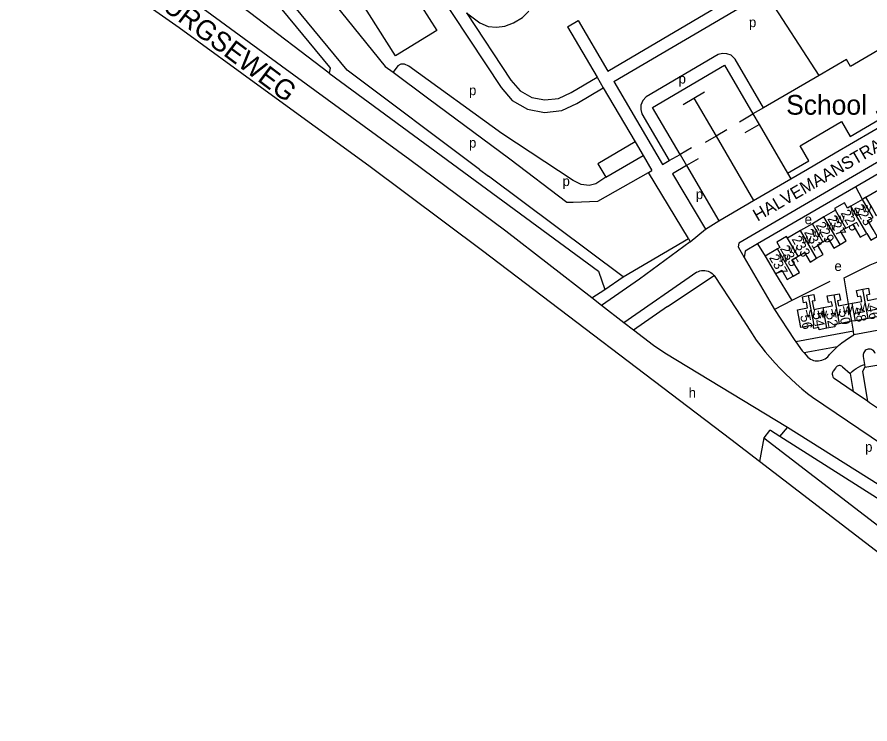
# Model space of a CAD drawing. Extents: x 158356 to 159894, y 383831 to 385260.
# Drawn here: x 158355.9 to 158701.2, y 383902.1 to 384188.4 of the extents above; entities that cross this region are included whole.
import ezdxf

# ---------------------------------------------------------------- set-up
doc = ezdxf.new("R2010")
doc.units = 0
for name, color, linetype in [('BLT_Basislijn', 7, 'Continuous'), ('BLT_Bebouwing', 7, 'Continuous'), ('BLT_Bebouwing_beschrifting', 7, 'Continuous'), ('BLT_Centroide', 7, 'Continuous'), ('BLT_Huisnummer', 7, 'Continuous'), ('BLT_Huisnummer_ tussenligend', 7, 'Continuous'), ('BLT_Onderdoorgang_en_onderverdeling', 7, 'Continuous'), ('BLT_Onderverdeling_panden', 7, 'Continuous'), ('BLT_Straatnaam', 7, 'Continuous'), ('BLT_Straatnaam_hoofdweg', 7, 'Continuous'), ('BLT_Vlakafsluiter', 7, 'Continuous')]:
    doc.layers.add(name, color=color, linetype=linetype)

msp = doc.modelspace()

# ---------------------------------------------------------------- linework, layer by layer
at = {"layer": 'BLT_Basislijn'}
for p, q in [((158578.7, 384184.41), (158583.01, 384186.94)), ((158578.7, 384184.41), (158590.72, 384163.98)), ((158583.01, 384186.94), (158595.03, 384166.51)), ((158639.73, 384173.14), (158610.57, 384156.06)), ((158508.16, 384166), (158522.06, 384155.66)), ((158593.25, 384159.67), (158606.12, 384137.79)), ((158597.56, 384162.2), (158617.27, 384128.7)), ((158629.9, 384155.55), (158634.25, 384158.12)), ((158522.06, 384155.66), (158555.35, 384130.9)), ((158625.56, 384152.99), (158629.9, 384155.55)), ((158629.9, 384155.55), (158638.9, 384140.17)), ((158648.4, 384145.96), (158653.81, 384149.12)), ((158643.26, 384142.74), (158638.9, 384140.17)), ((158650.71, 384141.6), (158656.29, 384144.87)), ((158638.9, 384140.17), (158634.53, 384137.6)), ((158638.9, 384140.17), (158654.09, 384114.05)), ((158606.12, 384137.79), (158609.34, 384132.32)), ((158629.01, 384135.4), (158624.32, 384132.73)), ((158594.23, 384123.49), (158609.34, 384132.32)), ((158609.34, 384132.32), (158612.93, 384126.22)), ((158619.98, 384130.25), (158624.32, 384132.73)), ((158624.32, 384132.73), (158626.93, 384128.25)), ((158617.27, 384128.7), (158619.98, 384130.25)), ((158631.6, 384131.01), (158626.93, 384128.25)), ((158543.13, 384126.68), (158546.72, 384123.99)), ((158611.5, 384125.4), (158612.93, 384126.22)), ((158627.68, 384098.63), (158611.5, 384125.4)), ((158626.93, 384128.25), (158621.25, 384124.9)), ((158621.25, 384124.9), (158634.57, 384102.4)), ((158626.93, 384128.25), (158640, 384105.85)), ((158667.8, 384125.16), (158669.15, 384122.83)), ((158601.25, 384083.15), (158546.72, 384123.99)), ((158654.09, 384114.05), (158669.15, 384122.83)), ((158695.47, 384119.63), (158655.72, 384096.51)), ((158698.19, 384114.54), (158695.47, 384119.63)), ((158699.54, 384115.39), (158698.19, 384114.54)), ((158640, 384105.85), (158654.09, 384114.05)), ((158634.57, 384102.4), (158640, 384105.85)), ((158588.63, 384074.62), (158553.77, 384101.62)), ((158628.45, 384097.36), (158634.57, 384102.4)), ((158601.25, 384083.15), (158627.68, 384098.63)), ((158655.72, 384096.51), (158658.75, 384091.51)), ((158631.15, 384085.02), (158601.61, 384064.57)), ((158619.3, 384071.18), (158638.1, 384083.74)), ((158662.9, 384084.37), (158669.59, 384073.64)), ((158593.84, 384078.08), (158601.25, 384083.15)), ((158684.93, 384081.32), (158669.59, 384073.64)), ((158588.63, 384074.62), (158593.84, 384078.08)), ((158592.55, 384071.59), (158588.63, 384074.62)), ((158669.59, 384073.64), (158662.55, 384069.96)), ((158601.61, 384064.57), (158592.55, 384071.59)), ((158619.3, 384071.18), (158605.45, 384061.6)), ((158662.55, 384069.96), (158670.49, 384057.77)), ((158605.45, 384061.6), (158601.61, 384064.57)), ((158694.48, 384061.13), (158693.9, 384065.16)), ((158727.11, 384065.73), (158694.69, 384059.64)), ((158694.48, 384061.13), (158671.22, 384056.78)), ((158694.69, 384059.64), (158694.48, 384061.13)), ((158687.89, 384054.81), (158674.59, 384052.32)), ((158674.59, 384052.32), (158676.02, 384050.63)), ((158698.46, 384050.9), (158698.96, 384047.67)), ((158687.31, 384046.22), (158686.35, 384044.98)), ((158690.15, 384046.77), (158693.23, 384044.02)), ((158699.14, 384046.54), (158698.16, 384044.84)), ((158698.96, 384047.67), (158699.14, 384046.54)), ((158699.14, 384046.54), (158704.05, 384047.44)), ((158693.23, 384044.02), (158694.45, 384036.7)), ((158698.16, 384044.84), (158700.18, 384032.75)), ((158694.45, 384036.7), (158686.76, 384041.95)), ((158699.39, 384033.33), (158694.45, 384036.7)), ((158677.95, 384034.41), (158706.27, 384015.3)), ((158700.18, 384032.75), (158699.39, 384033.33)), ((158719.42, 383989.69), (158667.79, 384022.18)), ((158656.47, 384008.34), (158644.82, 384017.27)), ((158733.69, 383949.17), (158656.47, 384008.34))]:
    msp.add_line(p, q, dxfattribs=at)
for points in [[(158411.05, 384254.61), (158482.47, 384168.03), (158482.74, 384167.63), (158482.31, 384165.65)], [(158482.31, 384165.65), (158417.72, 384214.84), (158386.28, 384237.31), (158383.92, 384237.99), (158377.96, 384236.95)], [(158499.82, 384238.62), (158551.85, 384159.77), (158556.33, 384154.59), (158562.5, 384151.05), (158569.43, 384149.73), (158576.44, 384150.51), (158582.59, 384153.39), (158593.25, 384159.67)], [(158498.33, 384128.13), (158454.84, 384159.75), (158421.6, 384183.98), (158374.82, 384216.83), (158355.92, 384229.65)], [(158553.77, 384101.62), (158514.89, 384130.54), (158462.93, 384168.42), (158432.71, 384190.6), (158412.8, 384204.65), (158387.75, 384219.8), (158378.82, 384225.15)], [(158680.64, 384164.75), (158659.4, 384197.49), (158701.12, 384225.27)], [(158595.03, 384166.51), (158651.21, 384199.6), (158654.32, 384201.89), (158656.74, 384204.69), (158658.46, 384207.97), (158659.42, 384211.54), (158659.55, 384215.25), (158658.88, 384218.88), (158657.33, 384222.31)], [(158597.56, 384162.2), (158653.97, 384195.42), (158657.73, 384198.2), (158660.9, 384201.85), (158663.14, 384206.13), (158664.4, 384210.8), (158664.57, 384215.62), (158663.68, 384220.38), (158662.9, 384222.13)], [(158466.15, 384216.37), (158504.98, 384168.37), (158508.16, 384166)], [(158543.13, 384126.68), (158489.58, 384166.83), (158454.86, 384208.9)], [(158537.85, 384190.07), (158543.32, 384186.02), (158546.64, 384184.5), (158550, 384184.31), (158553.33, 384184.72), (158556.89, 384186.05), (158560.48, 384188.16), (158563.05, 384190.76)], [(158537.85, 384190.07), (158555.85, 384162.79), (158559.56, 384158.5), (158564.26, 384155.81), (158569.63, 384154.79), (158575.07, 384155.39), (158580.26, 384157.82), (158590.72, 384163.98)], [(158785.32, 384174.66), (158783.94, 384176.68), (158782.64, 384177.18), (158781.63, 384177.11), (158748.8, 384155.41), (158738.53, 384149.56), (158648.13, 384096.77), (158647.84, 384095.35), (158650.22, 384090.93)], [(158658.13, 384151.64), (158646.57, 384171.36), (158645.01, 384172.86), (158643.29, 384173.53), (158641.55, 384173.66), (158639.73, 384173.14)], [(158594.23, 384123.49), (158590.29, 384120.86), (158587.52, 384120.11), (158584.23, 384120.53), (158581.09, 384122.15), (158552.15, 384141.15), (158514.49, 384168.51), (158512.8, 384169.31), (158511.27, 384169.25), (158510.07, 384168.54), (158508.16, 384166)], [(158624.32, 384132.73), (158613.1, 384151.74), (158642.26, 384168.83), (158653.81, 384149.12)], [(158482.31, 384165.65), (158591.31, 384085.44), (158593.84, 384078.08)], [(158610.57, 384156.06), (158609.22, 384154.59), (158608.39, 384152.68), (158608.39, 384150.92), (158608.8, 384149.2), (158619.98, 384130.25)], [(158669.15, 384122.83), (158675.92, 384126.78), (158687.07, 384133.33), (158709.41, 384146.37)], [(158745.84, 384148.93), (158695.47, 384119.63)], [(158606.12, 384137.79), (158591.01, 384128.98), (158594.23, 384123.49)], [(158555.35, 384130.9), (158578.51, 384113.34), (158581.11, 384113.43)], [(158644.82, 384017.27), (158544.29, 384093.64), (158498.33, 384128.13)], [(158581.11, 384113.43), (158591.1, 384113.76), (158611.5, 384125.4)], [(158627.68, 384098.63), (158628.45, 384097.36), (158607.85, 384082.24), (158592.55, 384071.59)], [(158655.72, 384096.51), (158650.65, 384093.56), (158650.22, 384090.93)], [(158650.22, 384090.93), (158662.55, 384069.96)], [(158692.58, 384072.17), (158690.7, 384082.78), (158701.23, 384088.02), (158711.39, 384092.06)], [(158631.15, 384085.02), (158631.75, 384085.31), (158632.38, 384085.53), (158633.02, 384085.67), (158633.69, 384085.73), (158634.35, 384085.71), (158635.01, 384085.61), (158635.65, 384085.43), (158636.26, 384085.18), (158636.84, 384084.86), (158637.37, 384084.46), (158637.86, 384084.01), (158638.1, 384083.74)], [(158638.1, 384083.74), (158647.2, 384069.92), (158652.62, 384061.54), (158655.16, 384057.52)], [(158667.79, 384022.18), (158618.2, 384052.31), (158613.52, 384055.34), (158605.45, 384061.6)], [(158687.89, 384054.81), (158688.46, 384055.33), (158689.78, 384056.41), (158691.15, 384057.43), (158692.56, 384058.38), (158694.02, 384059.27), (158694.69, 384059.64)], [(158655.16, 384057.52), (158656.97, 384055.12), (158658.84, 384052.78), (158660.78, 384050.48), (158662.78, 384048.24), (158664.83, 384046.05), (158666.95, 384043.91), (158669.12, 384041.84), (158671.34, 384039.82), (158673.62, 384037.86), (158675.95, 384035.96), (158677.95, 384034.41)], [(158670.49, 384057.77), (158671.22, 384056.78)], [(158671.22, 384056.78), (158673.82, 384053.24), (158674.59, 384052.32)], [(158684.83, 384051.73), (158685.98, 384052.99), (158687.2, 384054.19), (158687.89, 384054.81)], [(158703.31, 384052.16), (158703.13, 384052.57), (158702.88, 384052.95), (158702.57, 384053.27), (158702.21, 384053.53), (158701.81, 384053.73), (158701.38, 384053.85), (158700.93, 384053.89), (158700.48, 384053.85), (158700.05, 384053.73), (158699.65, 384053.54), (158699.28, 384053.28), (158698.97, 384052.96), (158698.72, 384052.58), (158698.54, 384052.17), (158698.44, 384051.74), (158698.42, 384051.29), (158698.46, 384050.9)], [(158676.02, 384050.63), (158676.55, 384050.2), (158677.13, 384049.83), (158677.75, 384049.54), (158678.4, 384049.32), (158679.07, 384049.18), (158679.75, 384049.11), (158680.43, 384049.13), (158681.11, 384049.23), (158681.77, 384049.4), (158682.41, 384049.65), (158683.01, 384049.98), (158683.57, 384050.37), (158684.09, 384050.82), (158684.54, 384051.33), (158684.83, 384051.73)], [(158690.15, 384046.77), (158689.83, 384046.98), (158689.47, 384047.13), (158689.09, 384047.2), (158688.71, 384047.19), (158688.33, 384047.1), (158687.98, 384046.93), (158687.68, 384046.7), (158687.42, 384046.41), (158687.31, 384046.22)], [(158693.23, 384044.02), (158693.99, 384044.76), (158694.82, 384045.45), (158695.68, 384046.07), (158696.6, 384046.62), (158697.55, 384047.11), (158698.54, 384047.52), (158698.96, 384047.67)], [(158686.76, 384041.95), (158686.48, 384042.32), (158686.26, 384042.73), (158686.12, 384043.17), (158686.06, 384043.62), (158686.07, 384044.09), (158686.17, 384044.54), (158686.35, 384044.98)], [(158706.34, 384028.61), (158701.03, 384032.11), (158700.18, 384032.75)], [(158660.93, 384020.95), (158660.58, 384020.88), (158658.2, 384017.9)], [(158658.2, 384017.9), (158708.3, 383979.52), (158740.71, 383955.02), (158752.16, 383946.49), (158811.09, 383902.1)], [(158664.77, 384018.5), (158660.93, 384020.95)], [(158735.9, 383973.27), (158664.77, 384018.5)]]:
    msp.add_lwpolyline(points, dxfattribs=at)
msp.add_lwpolyline([(158484.6, 384211.57), (158501.08, 384221.87), (158525.85, 384182.86), (158509.08, 384172.69)], close=True, dxfattribs=at)
at = {"layer": 'BLT_Bebouwing'}
for p, q in [((158680.64, 384164.75), (158658.13, 384151.64)), ((158658.13, 384151.64), (158653.81, 384149.12)), ((158653.81, 384149.12), (158656.29, 384144.87)), ((158656.29, 384144.87), (158667.8, 384125.16)), ((158699.54, 384115.39), (158704.7, 384118.39)), ((158698.19, 384114.54), (158693.46, 384111.78)), ((158687.22, 384110.1), (158682.59, 384107.41)), ((158677.88, 384104.66), (158673.07, 384101.86)), ((158682.59, 384107.41), (158677.88, 384104.66)), ((158673.07, 384101.86), (158667.84, 384098.81)), ((158663.77, 384094.44), (158658.75, 384091.51)), ((158658.75, 384091.51), (158662.9, 384084.37)), ((158692.58, 384072.17), (158694, 384072.44)), ((158700.42, 384066.32), (158695.34, 384065.36)), ((158705.5, 384067.27), (158700.42, 384066.32)), ((158693.9, 384065.16), (158688.77, 384064.19)), ((158695.34, 384065.36), (158693.9, 384065.16))]:
    msp.add_line(p, q, dxfattribs=at)
for points in [[(158667.8, 384125.16), (158676.4, 384130.2), (158672.9, 384136.25), (158689.65, 384146.01), (158693.17, 384139.96), (158705.59, 384147.24), (158703.87, 384150.07), (158727.74, 384164), (158724.56, 384169.43), (158722.43, 384168.03), (158718.12, 384175.42), (158720.33, 384176.7), (158717.13, 384182.18), (158693.28, 384168.27), (158691.73, 384171.21), (158680.64, 384164.75)], [(158702.49, 384107.17), (158700.71, 384110.22), (158698.19, 384114.54)], [(158711.15, 384107.09), (158712.66, 384104.41), (158710.25, 384103.05), (158708.69, 384105.66), (158706.48, 384109.44), (158703.89, 384107.93), (158702.06, 384111.07), (158699.54, 384115.39)], [(158693.46, 384111.78), (158692.14, 384111.02), (158690.91, 384113.14), (158686.84, 384110.77), (158687.22, 384110.1)], [(158691.46, 384102.82), (158694.21, 384104.42), (158697.24, 384099.21), (158699.88, 384100.74)], [(158699.88, 384100.74), (158701.6, 384098.03), (158704.12, 384099.55), (158702.52, 384102.28), (158700.39, 384105.95), (158702.49, 384107.17)], [(158689.1, 384096.23), (158691.62, 384097.69), (158689.34, 384101.59), (158691.46, 384102.82)], [(158667.84, 384098.81), (158667.47, 384099.44), (158663.52, 384097.14), (158664.76, 384095.01), (158663.77, 384094.44)], [(158679.58, 384090.68), (158682.19, 384092.21), (158679.94, 384096.08), (158682.13, 384097.36)], [(158682.13, 384097.36), (158684.33, 384098.64), (158686.59, 384094.76), (158689.1, 384096.23)], [(158670.17, 384083.46), (158672.62, 384084.89), (158669.62, 384090.03), (158672.17, 384091.52)], [(158672.17, 384091.52), (158674.72, 384093.01), (158676.96, 384089.16), (158679.58, 384090.68)], [(158662.9, 384084.37), (158665.48, 384085.87), (158667.71, 384082.04), (158670.17, 384083.46)], [(158694, 384072.44), (158697.89, 384073.17), (158697.49, 384075.29), (158696.3, 384075.07), (158695.81, 384077.65), (158698.27, 384078.11)], [(158698.27, 384078.11), (158700.55, 384078.54), (158701.03, 384075.96), (158699.85, 384075.74), (158700.25, 384073.62), (158704.16, 384074.35)], [(158678.26, 384063.55), (158673.26, 384062.61), (158671.9, 384069.83), (158675.87, 384070.58), (158675.45, 384072.84), (158674.33, 384072.63), (158673.86, 384075.11), (158676.16, 384075.55)], [(158676.16, 384075.55), (158678.48, 384075.99), (158678.95, 384073.5), (158677.83, 384073.29), (158678.45, 384069.97), (158682.23, 384070.68)], [(158682.23, 384070.68), (158686, 384071.39), (158685.68, 384073.07), (158684.37, 384072.82), (158683.89, 384075.4), (158686.53, 384075.9)], [(158686.53, 384075.9), (158688.73, 384076.31), (158689.21, 384073.73), (158688, 384073.51), (158688.4, 384071.38), (158692.58, 384072.17)], [(158683.8, 384062.36), (158680.62, 384061.76), (158680.46, 384062.6), (158678.5, 384062.23), (158678.26, 384063.55)], [(158688.77, 384064.19), (158686.83, 384063.82), (158686.99, 384062.96), (158683.8, 384062.36)]]:
    msp.add_lwpolyline(points, dxfattribs=at)
at = {"layer": 'BLT_Onderdoorgang_en_onderverdeling'}
for points in [[(158693.9, 384065.16), (158692.98, 384070.07), (158692.58, 384072.17)], [(158695.34, 384065.36), (158694.41, 384070.27), (158694, 384072.44)]]:
    msp.add_lwpolyline(points, dxfattribs=at)
at = {"layer": 'BLT_Onderverdeling_panden'}
for p, q in [((158699.88, 384100.74), (158693.46, 384111.78)), ((158691.46, 384102.82), (158687.22, 384110.1)), ((158682.13, 384097.36), (158677.88, 384104.66)), ((158689.1, 384096.23), (158682.59, 384107.41)), ((158679.58, 384090.68), (158673.07, 384101.86)), ((158672.17, 384091.52), (158667.84, 384098.81)), ((158670.17, 384083.46), (158663.77, 384094.44)), ((158700.42, 384066.32), (158698.27, 384078.11)), ((158686.53, 384075.9), (158688.77, 384064.19)), ((158683.8, 384062.36), (158682.23, 384070.68))]:
    msp.add_line(p, q, dxfattribs=at)
msp.add_lwpolyline([(158676.16, 384075.55), (158678.42, 384063.58), (158678.26, 384063.55)], dxfattribs=at)
at = {"layer": 'BLT_Vlakafsluiter'}
for p, q in [((158590.72, 384163.98), (158593.25, 384159.67)), ((158664.77, 384018.5), (158667.79, 384022.18)), ((158658.2, 384017.9), (158656.47, 384008.34))]:
    msp.add_line(p, q, dxfattribs=at)

# ---------------------------------------------------------------- texts
at = {"layer": 'BLT_Bebouwing_beschrifting'}
msp.add_text('School', height=8, rotation=359.9995, dxfattribs=at).set_placement((158667.27, 384148.82))
at = {"layer": 'BLT_Centroide'}
for s, p in [('p', (158652.21, 384184.26)), ('p', (158623.73, 384161.43)), ('p', (158538.88, 384156.72)), ('p', (158538.88, 384135.47)), ('p', (158576.74, 384119.92)), ('p', (158630.69, 384114.65)), ('w', (158697.98, 384109.22)), ('e', (158674.74, 384104.48)), ('w', (158687.11, 384104.84)), ('w', (158693.36, 384107.83)), ('w', (158683.5, 384102)), ('w', (158677.62, 384099.28)), ('w', (158673.7, 384096.58)), ('w', (158668.06, 384092.75)), ('w', (158664.45, 384089.27)), ('e', (158686.82, 384085.54)), ('w', (158675.16, 384066.7)), ('w', (158685.5, 384067)), ('w', (158690.22, 384068.09)), ('w', (158693.92, 384067.65)), ('w', (158697.2, 384069.38)), ('w', (158679.98, 384066.38)), ('h', (158627.8, 384034.24)), ('p', (158699.24, 384012.33))]:
    msp.add_text(s, height=4, dxfattribs=at).set_placement(p)
at = {"layer": 'BLT_Huisnummer'}
for s, rotation, p in [('223', 300.2173, (158694.72, 384111.19)), ('227', 300.2173, (158683.83, 384106.68)), ('231', 300.2173, (158674.39, 384101.18)), ('237', 300.2173, (158660.23, 384090.9)), ('50', 280.6809, (158688.46, 384069.35)), ('48', 280.6809, (158694.89, 384070.43)), ('56', 280.6809, (158672.95, 384067.44))]:
    msp.add_text(s, height=4, rotation=rotation, dxfattribs=at).set_placement(p)
at = {"layer": 'BLT_Huisnummer_ tussenligend'}
for s, rotation, p in [('225', 300.2173, (158689.18, 384108.97)), ('229', 300.2173, (158679.11, 384104.04)), ('233', 300.2173, (158669.38, 384098.42)), ('235', 300.2173, (158664.65, 384094.56)), ('46', 280.6809, (158700.05, 384071.43)), ('54', 280.6809, (158677.95, 384068.42)), ('52', 280.6809, (158683.33, 384068.4))]:
    msp.add_text(s, height=4, rotation=rotation, dxfattribs=at).set_placement(p)
at = {"layer": 'BLT_Straatnaam'}
msp.add_text('HALVEMAANSTRAAT', height=5, rotation=30.0829, dxfattribs=at).set_placement((158655.66, 384105.49))
at = {"layer": 'BLT_Straatnaam_hoofdweg'}
msp.add_text('TILBURGSEWEG', height=8, rotation=323.056, dxfattribs=at).set_placement((158396.3, 384205.29))

doc.saveas('drawing.dxf')
